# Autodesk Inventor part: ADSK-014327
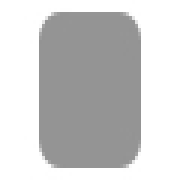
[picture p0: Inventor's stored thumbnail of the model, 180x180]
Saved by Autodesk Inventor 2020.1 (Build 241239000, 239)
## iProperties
Created: 2019-01
Part Number: ADSK-014327
Material: Stahl, weich
Document SubType Name: Modeling
Designer: lutzd
Language: de-DE
Size Designation: 5 x 39,384472 x 39,384472
Categories: <MemberInstance><Categories><Category DisplayName="Sonstige Bauteile" InternalName="5aa15e00-363f-49f2-933f-16f664388e3f" Mnemonic="OTHER"><Category DisplayName
Mass: 60.0398 g
Surface Area: 38.0412 cm^2
Volume: 7.64838 cm^3
Density: 7.85 g/cm^3
Appearance: Semi-Polished(8)
IsCustomPart: 1
Title: end cap
Author: lutzd
Revision Number: -
Dimensions: 39,4x39,4x5 mm
Mass: 0,06 kg
DocNumber: ADSK-014327
Folder: 01 - Themengebiete\Simplification\01 - Packaging machine\ADSK-014261\Frame\
VDS_Category: 3D Komponenten
VDS_NumSchm: Autodesk
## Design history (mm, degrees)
sketch "Sketch1"
  geometry: L1 (0, 20.175)-(0, -21.446); L2 (-20.203, 0)-(20.169, 0); L3 (-19.692, 19.692)-(19.692, 19.692); L4 (19.692, 19.692)-(19.692, -19.692); L5 (19.692, -19.692)-(-19.692, -19.692); L6 (-19.692, -19.692)-(-19.692, 19.692); 1 further point
  constraints: 12 end point, 2 horizontal, 2 parallel, 2 point on line, 1 perpendicular, 1 vertical
  dimensions: "d0" = 39.38447 distance between parallel lines of L5 L3 (= height); "d1" = 19.69224 distance between parallel lines of L2 L3 (= 0.5 x height); "d2" = 39.38447 distance between parallel lines of L6 L4 (= width); "d3" = 19.69224 distance between parallel lines of L6 L1 (= 0.5 x width)
extrude "Extrusion1" new body sketch "Sketch1" distance "d4" = 5 (= thickness); taper "d5" = 0 deg
fillet "Fillet1" dims "d6" = 5 (= fillet), "d7" = 0, "fillet" = 5 [user parameter; used in 1 equation term]
chamfer "Chamfer1" distance "d8" = 0 (computed from chamfer); stored, may be unused: second distance "d9" = 2, angle "d10" = 45 deg; dims "d11" = 0, "chamfer" = 0 [user parameter; used in 1 equation term]
body "Solid1"
other parameters: "thickness" = 5 [user parameter; used in 1 equation term], "width" = 39.38447 [user parameter; used in 2 equation terms], "height" = 39.38447 [user parameter; used in 2 equation terms]
